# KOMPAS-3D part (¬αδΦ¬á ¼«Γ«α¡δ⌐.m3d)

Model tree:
1. Эскиз:1
2. Операция выдавливания:1
     Расстояние 1 = 2; Расстояние 2 = 0.3
3. Эскиз:2
4. Операция выдавливания:2
     Расстояние 1 = 2.5; Угол 1 = 22; Расстояние 2 = 1
5. Эскиз:3
6. Операция выдавливания:3
     Расстояние 1 = 2; Расстояние 2 = 1
7. Эскиз:4
8. Операция выдавливания:4
     Расстояние 1 = 0.5; Расстояние 2 = 1
9. Эскиз:5
10. Операция выдавливания:5
     Расстояние 1 = 0.5; Расстояние 2 = 1
11. Скругление:1
     Радиус = 3
12. Скругление:2
     Радиус = 3
13. Скругление:3
     Радиус = 1
14. Скругление:4
     Радиус = 0.5
15. Скругление:5
     Радиус = 0.5
16. Скругление:6
     Радиус = 0.5
17. Эскиз:6
18. Вырезать элемент выдавливания:1
     Расстояние 1 = 3
19. Эскиз:7
20. Операция выдавливания:6
     Расстояние 1 = 4; Расстояние 2 = 1
21. Эскиз:8
22. Операция выдавливания:7
     Расстояние 1 = 0.5; Расстояние 2 = 1
23. Скругление:7
     Радиус = 0.5
24. Эскиз:9
25. Вырезать элемент выдавливания:2
     Расстояние 1 = 3
26. Массив по сетке:1  (with: Вырезать элемент выдавливания:2)  (labels: Экземпляр ( 1, 1 ); Экземпляр ( 2, 1 ); Экземпляр ( 3, 1 ); Экземпляр ( 4, 1 ))
     N 1 = 4; Шаг 1 = 109; Угол раствора = 90; N 2 = 1; Номер 1 = 1; Номер 2 = 1
27. Эскиз:10
28. Операция выдавливания:8
     Расстояние 1 = 5; Расстояние 2 = 1
29. Эскиз:11
30. Операция выдавливания:9
     Расстояние 1 = 3; Расстояние 2 = 0.5
31. Эскиз:12
32. Вырезать элемент выдавливания:3
     Расстояние 1 = 3
33. Скругление:8
     Радиус = 1.5
34. Массив по сетке:2  (with: Операция выдавливания:8, Операция выдавливания:9, Вырезать элемент выдавливания:3, Скругление:8)  (labels: Экземпляр ( 1, 1 ); Экземпляр ( 2, 1 ); Экземпляр ( 3, 1 ); Экземпляр ( 4, 1 ))
     N 1 = 4; Шаг 1 = 109; Угол раствора = 90; N 2 = 1; Номер 1 = 1; Номер 2 = 1
35. Эскиз:13
36. Операция выдавливания:10
     Расстояние 1 = 4; Расстояние 2 = 0.5
37. Эскиз:14
38. Операция выдавливания:11
     Расстояние 1 = 114.5; Расстояние 2 = 7
39. Скругление:9
     Радиус = 1.5
40. Эскиз:15
41. Операция выдавливания:12
     Расстояние 1 = 114.5; Расстояние 2 = 0.5
42. Эскиз:16
43. Операция выдавливания:13
     Расстояние 1 = 7; Расстояние 2 = 7
44. Эскиз:17
45. Операция выдавливания:14
     Расстояние 1 = 7; Расстояние 2 = 27.9
46. Эскиз:18
47. Вырезать элемент выдавливания:4
     Расстояние 1 = 0.3
48. Скругление:10
     Радиус = 0.2
49. Эскиз:19
50. Вырезать элемент выдавливания:5
     Расстояние 1 = 0.1
51. Скругление:11
     Радиус = 0.1
52. Эскиз:20
53. Операция выдавливания:15
     Расстояние 1 = 4.5; Расстояние 2 = 27.9
54. Эскиз:21
55. Вырезать элемент выдавливания:6
     Расстояние 1 = 3.5
56. Скругление:12
     Радиус = 2
57. Эскиз:22
58. Операция выдавливания:16
     Расстояние 1 = 0.2; Расстояние 2 = 5.2
59. Эскиз:23
60. Операция выдавливания:17
     Расстояние 1 = 0.2; Расстояние 2 = 5.2
61. Эскиз:24
62. Операция выдавливания:18
     Расстояние 1 = 0.2; Расстояние 2 = 5
63. Эскиз:25
64. Операция выдавливания:19
     Расстояние 1 = 0.2; Расстояние 2 = 5
65. Эскиз:26
66. Операция выдавливания:20
     Расстояние 1 = 2; Расстояние 2 = 2
67. Скругление:13
     Радиус = 2
68. Скругление:14
     Радиус = 0.5
69. Эскиз:27
70. Вырезать элемент выдавливания:7
     Расстояние 2 = 10
71. Эскиз:28
72. Операция выдавливания:21
     Расстояние 1 = 0.2; Расстояние 2 = 118.3
73. Эскиз:29
74. Вырезать элемент выдавливания:8
     Расстояние 1 = 0.5
75. Эскиз:30
76. Операция выдавливания:22
     Расстояние 1 = 0.7; Расстояние 2 = 118.3
77. Эскиз:31
78. Операция выдавливания:23
     Расстояние 1 = 1; Расстояние 2 = 118.3
79. Эскиз:32
80. Операция выдавливания:24
     Расстояние 1 = 0.5; Расстояние 2 = 118.3
81. Эскиз:33
82. Операция выдавливания:25
     Расстояние 1 = 0.5; Расстояние 2 = 118.3
83. Эскиз:34
84. Вырезать элемент выдавливания:9
     Расстояние 1 = 0.2
85. Эскиз:35
86. Операция выдавливания:26
     Расстояние 1 = 0.5; Расстояние 2 = 118.3
87. Эскиз:36
88. Операция выдавливания:27
     Расстояние 1 = 1; Расстояние 2 = 118.3
89. Эскиз:37
90. Операция выдавливания:28
     Расстояние 1 = 0.5; Расстояние 2 = 118.3
91. Эскиз:38
92. Операция выдавливания:29
     Расстояние 1 = 0.5; Расстояние 2 = 118.3
93. Эскиз:39
94. Вырезать элемент выдавливания:10
     Расстояние 1 = 0.2
95. Эскиз:40
96. Операция выдавливания:30
     Расстояние 1 = 1; Расстояние 2 = 118.3
97. Эскиз:41
98. Вырезать элемент выдавливания:11
     Расстояние 1 = 1
99. Эскиз:42
100. Вырезать элемент выдавливания:12
     Расстояние 1 = 0.2
101. Смещенная плоскость:1
     Расстояние = 0.1
102. Эскиз:43
103. Операция выдавливания:31
     Расстояние 1 = 1; Расстояние 2 = 0.2
104. Эскиз:44
105. Вырезать элемент выдавливания:13
     Расстояние 1 = 0.2
106. Вырезать элемент выдавливания:14
     Расстояние 1 = 0.2
107. Массив по сетке:4  (with: Вырезать элемент выдавливания:14)  (labels: Экземпляр ( 1, 1 ); Экземпляр ( 2, 1 ); Экземпляр ( 3, 1 ); Экземпляр ( 4, 1 ))
     N 1 = 18; Шаг 1 = 3; Угол раствора = 90; N 2 = 1; Номер 1 = 1; Номер 2 = 1
108. Эскиз:45
109. Вырезать элемент выдавливания:15
     Расстояние 1 = 0.2
110. Массив по сетке:5  (with: Вырезать элемент выдавливания:15)  (labels: Экземпляр ( 1, 1 ); Экземпляр ( 2, 1 ); Экземпляр ( 3, 1 ); Экземпляр ( 4, 1 ))
     N 1 = 19; Шаг 1 = 1.2; Угол раствора = 90; N 2 = 1; Номер 1 = 1; Номер 2 = 1
111. Эскиз:46
112. Операция выдавливания:32
     Расстояние 1 = 1; Расстояние 2 = 0.2
113. Эскиз:47
114. Операция выдавливания:33
     Расстояние 1 = 0.3; Расстояние 2 = 0.3
115. Эскиз:48
116. Операция выдавливания:34
     Расстояние 1 = 0.5; Расстояние 2 = 0.3
117. Эскиз:49
118. Операция выдавливания:35
     Расстояние 1 = 3; Расстояние 2 = 0.3
119. Массив по сетке:7  (with: Операция выдавливания:34, Операция выдавливания:33)  (labels: Экземпляр ( 1, 1 ); Экземпляр ( 2, 1 ); Экземпляр ( 3, 1 ); Экземпляр ( 4, 1 ))
     Наклон = 180; N 1 = 6; Шаг 1 = 20; Угол раствора = 90; N 2 = 1; Номер 1 = 1; Номер 2 = 1

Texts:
  Сплав АЛ8  ГОСТ 1583-93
